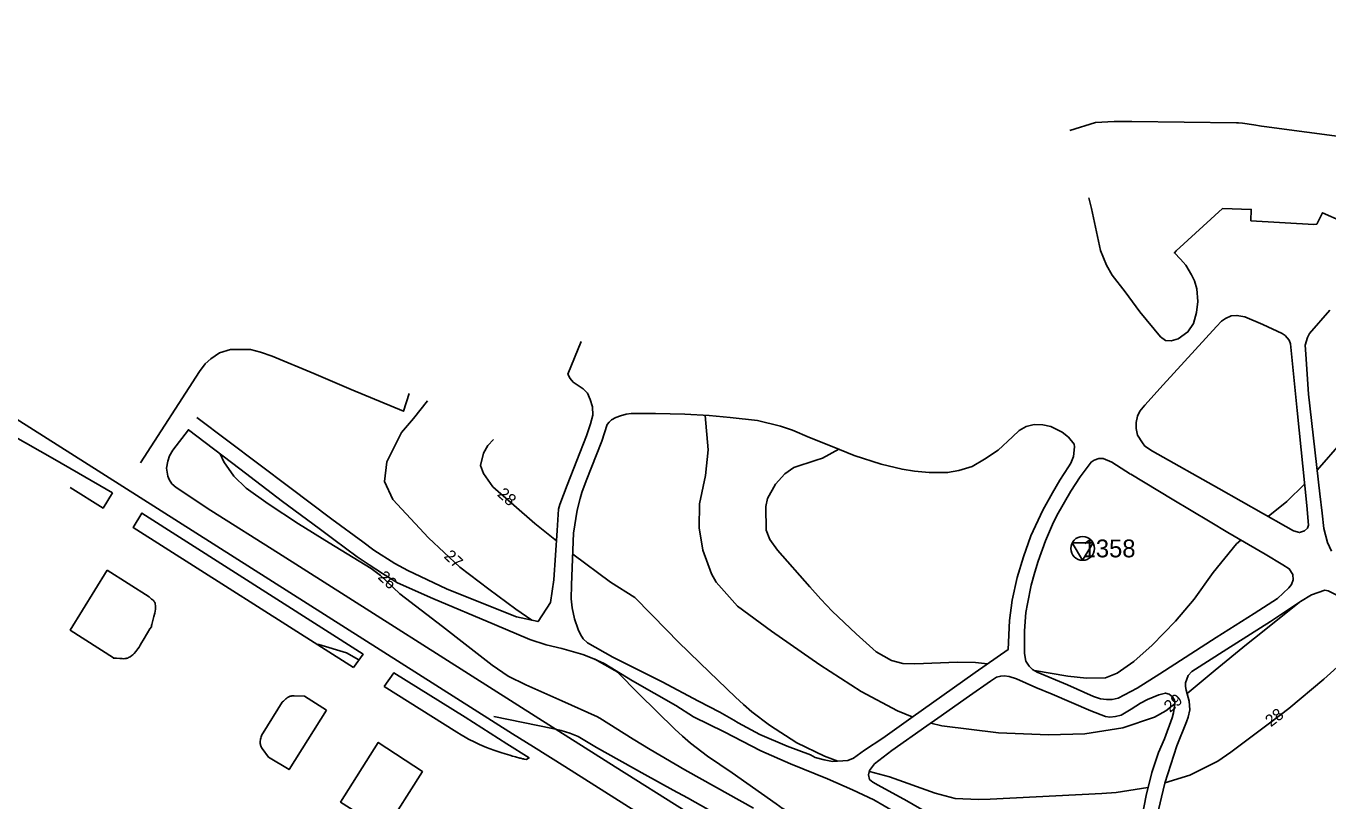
# Model space of a CAD drawing. Extents: x 67169 to 69652, y 20189 to 22818.
# Drawn here: x 69252.8 to 69362.6, y 21251.9 to 21317.2 of the extents above; entities that cross this region are included whole.
import ezdxf

# ---------------------------------------------------------------- set-up
doc = ezdxf.new("R2010")
doc.units = 0
for name, color, linetype in [('HOJDKURVOR_2014', 7, 'Continuous'), ('HOJDKURVOR_2014 5M', 7, 'Continuous'), ('HOJDKURVOR_TEXTER_2014', 7, 'Continuous'), ('MUR_STAKET', 7, 'Continuous'), ('MUR_STAKET_SYMBOL', 7, 'Continuous'), ('STOMPUNKTER', 7, 'Continuous'), ('STOMPUNKTER TEXT', 7, 'Continuous'), ('VAGAR 121', 7, 'Continuous'), ('VAGAR 123', 7, 'Continuous')]:
    doc.layers.add(name, color=color, linetype=linetype)

msp = doc.modelspace()

# ---------------------------------------------------------------- linework, layer by layer
at = {"layer": 'HOJDKURVOR_2014'}
for points in [[(69295.5, 21267.14), (69294.15, 21268.08), (69291.86, 21269.76), (69289.42, 21271.6), (69286.77, 21274.09), (69283.78, 21277.32), (69283.07, 21278.83), (69283.28, 21280.48), (69284.51, 21282.97), (69285.52, 21284.14), (69286.69, 21285.64)], [(69327.58, 21258.98), (69326.35, 21259.5), (69323.27, 21261.14), (69319.78, 21263.37), (69315.7, 21266.21), (69312.83, 21268.33), (69311.04, 21270.35), (69310.64, 21271.04), (69309.93, 21273.04), (69309.6, 21274.94), (69309.65, 21276.96), (69310.14, 21279.35), (69310.36, 21281.49), (69310.12, 21284.41)], [(69297.57, 21273.84), (69295.75, 21275.3), (69292.22, 21278.38), (69291.42, 21279.5), (69291.18, 21280.17), (69291.41, 21281.23), (69291.8, 21281.88), (69292.25, 21282.37)], [(69314.18, 21251.29), (69309.86, 21253.7), (69308.39, 21254.53), (69305.49, 21256.24), (69304.05, 21257.12), (69301.22, 21258.87), (69301.18, 21258.9), (69301.04, 21258.98), (69298.04, 21260.35), (69294.99, 21261.69), (69293.51, 21262.43), (69292.14, 21263.36), (69289.88, 21265.12), (69287.97, 21266.61), (69284.36, 21269.36), (69282.72, 21270.9), (69281.95, 21271.51), (69278.41, 21273.66), (69275.82, 21275.27), (69273.27, 21276.94), (69271.39, 21278.26), (69270.35, 21279.28), (69269.51, 21280.49), (69269.22, 21281.16)], [(69321.31, 21255.26), (69320.19, 21255.68), (69317.84, 21256.8), (69315.55, 21258.29), (69314.06, 21259.41), (69313.36, 21260.02), (69312.67, 21260.65), (69309.69, 21263.52), (69307.82, 21265.34), (69306.9, 21266.26), (69304.17, 21269.05), (69302.14, 21270.34), (69298.96, 21272.72), (69298.95, 21272.73)], [(69360.24, 21268.66), (69357.12, 21266.17), (69355.78, 21265.09), (69353.12, 21262.92), (69350.76, 21260.95)], [(69367.18, 21266.97), (69366.94, 21266.61), (69366.26, 21265.82), (69366.01, 21265.58), (69363.7, 21263.44), (69362.28, 21262.16), (69359.34, 21259.7), (69357.82, 21258.53), (69354.45, 21256), (69353.34, 21255.26), (69350.98, 21254.07), (69348.89, 21253.43)], [(69335.63, 21244.51), (69333.62, 21244.76), (69330.22, 21245.44), (69325.91, 21246.41), (69323.33, 21247.47), (69321.93, 21248.26), (69321.65, 21248.41), (69316.55, 21251.33), (69316.42, 21251.42), (69316.1, 21251.65), (69312.4, 21254.27), (69310.31, 21255.68), (69308.89, 21256.76), (69308.21, 21257.35), (69307.56, 21257.95), (69304.51, 21260.93), (69302.71, 21262.76), (69302.54, 21262.88), (69302.5, 21262.91), (69300.81, 21263.85)], [(69349.73, 21260.09), (69349.51, 21259.91), (69348.97, 21259.49), (69348, 21258.96), (69345.33, 21258.05), (69342.13, 21257.55), (69339.07, 21257.46), (69334.86, 21257.64), (69330.09, 21258.24), (69329.16, 21258.47)], [(69347.46, 21253.02), (69344.77, 21252.62), (69343.57, 21252.54), (69334.14, 21252.06), (69333.16, 21252.03), (69331.2, 21252.1), (69329.52, 21252.55), (69325.65, 21253.92), (69323.97, 21254.39)]]:
    msp.add_lwpolyline(points, dxfattribs=at)
at = {"layer": 'HOJDKURVOR_2014 5M'}
for points in [[(69340.88, 21308.42), (69343.05, 21309.11), (69344.61, 21309.18), (69346.11, 21309.19), (69354.92, 21309.07), (69355.09, 21309.07), (69355.44, 21309.04), (69356.39, 21308.9), (69357.04, 21308.8), (69357.26, 21308.77), (69364.45, 21307.81)], [(69365.96, 21284.63), (69361.73, 21279.78)], [(69333.92, 21263.45), (69332.92, 21263.56), (69331.39, 21263.59), (69327.79, 21263.46), (69326.8, 21263.5), (69325.84, 21263.75), (69324.54, 21264.47), (69322.84, 21265.98), (69320.84, 21267.9), (69319.88, 21268.91), (69318.95, 21269.94), (69316.23, 21273.04), (69315.56, 21273.95), (69315.27, 21274.72), (69315.22, 21276.72), (69315.36, 21277.39), (69316.05, 21278.61), (69316.84, 21279.49), (69317.6, 21280.02), (69319.48, 21280.64), (69320, 21280.81), (69321.38, 21281.57)], [(69360.67, 21278.6), (69359.18, 21277.15), (69357.6, 21275.89)], [(69355.28, 21273.89), (69354.94, 21273.58), (69352.97, 21271.17), (69351.36, 21268.91), (69349.77, 21267.07), (69347.82, 21265.03), (69346.28, 21263.66), (69344.87, 21262.66), (69343.88, 21262.29), (69342.29, 21262.25), (69340.7, 21262.43), (69337.88, 21262.9)], [(69280.92, 21263.79), (69279.88, 21264.38), (69277.52, 21265.09), (69277.4, 21265.1)], [(69314.51, 21248.84), (69308.62, 21252.15), (69307.42, 21252.82), (69305.03, 21254.14), (69300.94, 21256.41), (69299.41, 21257.34), (69298.69, 21257.6), (69297.97, 21257.83), (69297.61, 21257.92), (69297.24, 21258.01), (69292.28, 21259.01)]]:
    msp.add_lwpolyline(points, dxfattribs=at)
at = {"layer": 'MUR_STAKET'}
for points in [[(69265.23, 21281.47), (69264.94, 21281.01), (69264.79, 21280.54), (69264.69, 21279.95), (69264.81, 21279.28), (69264.9, 21279.01), (69265.14, 21278.64), (69265.49, 21278.32), (69268.43, 21276.4), (69274.14, 21272.78), (69296.1, 21258.84)], [(69296.1, 21258.84), (69302.52, 21254.78), (69308.5, 21251), (69318.67, 21244.59), (69325.22, 21240.45), (69336.99, 21232.99), (69342.36, 21229.57), (69352.6, 21223.18), (69355.62, 21221.19), (69360.68, 21217.97), (69370.52, 21211.77), (69376.01, 21208.27), (69380.2, 21208.31), (69385.38, 21216.32)]]:
    msp.add_lwpolyline(points, dxfattribs=at)
at = {"layer": 'MUR_STAKET_SYMBOL'}
for p, q in [((69265.23, 21281.47), (69265.23, 21281.47)), ((69264.76, 21280.34), (69264.76, 21280.34)), ((69264.87, 21279.1), (69264.87, 21279.1)), ((69266.52, 21277.65), (69266.52, 21277.65)), ((69268.12, 21276.6), (69268.12, 21276.6)), ((69269.79, 21275.54), (69269.79, 21275.54)), ((69271.49, 21274.46), (69271.49, 21274.46)), ((69273.21, 21273.37), (69273.21, 21273.37)), ((69274.94, 21272.27), (69274.94, 21272.27)), ((69276.54, 21271.26), (69276.54, 21271.26)), ((69278.27, 21270.15), (69278.27, 21270.15)), ((69280.04, 21269.03), (69280.04, 21269.03)), ((69281.67, 21267.99), (69281.67, 21267.99)), ((69283.39, 21266.91), (69283.39, 21266.91)), ((69285.04, 21265.86), (69285.04, 21265.86)), ((69286.7, 21264.8), (69286.7, 21264.8)), ((69288.4, 21263.73), (69288.4, 21263.73)), ((69290.04, 21262.68), (69290.04, 21262.68)), ((69291.76, 21261.59), (69291.76, 21261.59)), ((69293.47, 21260.51), (69293.47, 21260.51)), ((69295.2, 21259.41), (69295.2, 21259.41)), ((69296.67, 21258.48), (69296.67, 21258.48)), ((69298.43, 21257.37), (69298.43, 21257.37)), ((69300.11, 21256.3), (69300.11, 21256.3)), ((69301.73, 21255.28), (69301.73, 21255.28)), ((69303.47, 21254.18), (69303.47, 21254.18)), ((69305.24, 21253.06), (69305.24, 21253.06)), ((69306.84, 21252.05), (69306.84, 21252.05))]:
    msp.add_line(p, q, dxfattribs=at)
at = {"layer": 'STOMPUNKTER'}
msp.add_lwpolyline([(69341.95, 21272.19), (69342.83, 21273.67), (69341.07, 21273.67)], close=True, dxfattribs=at)
msp.add_circle((69341.95, 21273.19), 1, dxfattribs=at)
at = {"layer": 'VAGAR 121'}
for p, q in [((69259.67, 21271.37), (69263.21, 21269.11)), ((69295.33, 21265.52), (69292.34, 21266.77)), ((69276.31, 21260.73), (69278.19, 21259.54))]:
    msp.add_line(p, q, dxfattribs=at)
for points in [[(69313.16, 21245.38), (69298.29, 21254.81), (69295.63, 21256.45), (69293.87, 21257.57), (69257.76, 21280.45), (69248.82, 21286.11), (69242.96, 21289.82), (69226.82, 21300.08), (69172.15, 21334.79)], [(69260.14, 21277.87), (69257.27, 21279.55), (69255.07, 21280.81), (69251.75, 21282.67), (69250.1, 21283.62), (69248.47, 21284.6), (69242.96, 21287.97), (69225.94, 21298.72), (69174.97, 21331.15), (69174.49, 21331.47), (69174.14, 21331.71), (69173.88, 21331.9), (69173.49, 21332.19), (69173.11, 21332.49), (69173.1, 21332.5)], [(69262.5, 21280.41), (69267.46, 21288.11), (69267.95, 21288.75), (69268.41, 21289.19), (69269.16, 21289.67), (69270.09, 21289.96), (69271.15, 21289.96), (69271.76, 21289.96), (69272.61, 21289.75), (69273.61, 21289.4), (69277.12, 21287.95), (69280.26, 21286.6), (69284.66, 21284.75), (69285.16, 21286.24)], [(69292.34, 21266.77), (69287.14, 21268.97), (69284.18, 21270.29), (69282.9, 21271.08), (69281.77, 21271.8), (69280.77, 21272.49), (69278.8, 21273.93), (69277.57, 21274.87), (69274.47, 21277.15), (69270.88, 21279.9), (69266.53, 21283.2), (69265.23, 21281.47)], [(69256.55, 21278.33), (69259.33, 21276.59), (69260.14, 21277.87)], [(69280.46, 21263.15), (69281.26, 21264.27), (69262.61, 21276.17), (69261.87, 21274.96), (69280.46, 21263.15)], [(69259.67, 21271.37), (69256.57, 21266.3), (69260.21, 21263.97)], [(69263.21, 21269.11), (69263.24, 21269.08), (69263.31, 21269.02), (69263.43, 21268.92), (69263.48, 21268.88), (69263.52, 21268.85), (69263.55, 21268.82), (69263.58, 21268.79), (69263.62, 21268.75), (69263.65, 21268.71), (69263.67, 21268.68), (69263.69, 21268.66), (69263.7, 21268.63), (69263.72, 21268.59), (69263.74, 21268.48), (69263.76, 21268.38), (69263.77, 21268.27), (69263.76, 21268.17), (69263.76, 21268.08), (69263.73, 21267.89), (69263.7, 21267.73), (69263.62, 21267.44), (69263.5, 21267), (69263.45, 21266.78), (69263.42, 21266.68), (69263.41, 21266.57)], [(69263.41, 21266.57), (69263.29, 21266.41), (69263.08, 21266.07), (69262.72, 21265.46), (69262.59, 21265.23), (69262.47, 21265.03), (69262.37, 21264.87), (69262.27, 21264.73), (69262.1, 21264.5), (69261.96, 21264.34), (69261.85, 21264.23), (69261.76, 21264.16), (69261.62, 21264.06), (69261.48, 21263.98), (69261.41, 21263.95), (69261.35, 21263.93), (69261.29, 21263.91), (69261.22, 21263.9), (69261.16, 21263.9), (69261.05, 21263.89), (69260.94, 21263.9), (69260.76, 21263.91), (69260.47, 21263.94), (69260.33, 21263.95), (69260.27, 21263.95), (69260.2, 21263.95)], [(69295.02, 21255.39), (69295.26, 21255.53), (69293.4, 21256.72), (69289.87, 21258.96), (69283.85, 21262.7), (69283.05, 21261.54)], [(69283.05, 21261.54), (69289.17, 21257.69), (69289.54, 21257.46), (69289.87, 21257.27), (69290.16, 21257.11), (69290.68, 21256.85), (69291.08, 21256.67), (69291.68, 21256.41), (69292.29, 21256.18), (69292.63, 21256.06), (69292.88, 21255.98), (69293.26, 21255.86), (69293.64, 21255.75), (69293.88, 21255.67), (69294, 21255.64), (69294.12, 21255.61), (69294.48, 21255.52), (69294.57, 21255.5), (69294.72, 21255.46), (69294.79, 21255.44), (69294.86, 21255.42), (69295.02, 21255.39)], [(69273.29, 21255.59), (69272.74, 21256.33), (69272.69, 21256.4), (69272.66, 21256.47), (69272.63, 21256.54), (69272.61, 21256.6), (69272.6, 21256.67), (69272.59, 21256.73), (69272.59, 21256.79), (69272.59, 21256.84), (69272.59, 21256.95), (69272.61, 21257.04), (69272.62, 21257.12), (69272.64, 21257.19), (69272.67, 21257.31), (69272.71, 21257.4), (69272.73, 21257.46), (69272.78, 21257.56), (69272.83, 21257.64), (69274.44, 21260.23)], [(69274.44, 21260.23), (69274.48, 21260.26), (69274.55, 21260.32), (69274.67, 21260.43), (69274.76, 21260.51), (69274.83, 21260.57), (69274.88, 21260.61), (69274.92, 21260.64), (69274.96, 21260.66), (69275, 21260.68), (69275.05, 21260.7), (69275.12, 21260.72), (69275.19, 21260.74), (69275.26, 21260.75), (69275.32, 21260.76), (69275.44, 21260.77), (69276.31, 21260.73)], [(69278.19, 21259.54), (69275.02, 21254.54), (69273.29, 21255.59)], [(69283.11, 21249.37), (69286.27, 21254.38), (69282.55, 21256.84), (69279.37, 21251.81), (69283.15, 21249.4)]]:
    msp.add_lwpolyline(points, dxfattribs=at)
at = {"layer": 'VAGAR 123'}
for points in [[(69363.83, 21300.75), (69362.18, 21301.5), (69361.7, 21300.53), (69361.45, 21300.5), (69356.15, 21300.82), (69356.17, 21301.77), (69353.75, 21301.86), (69349.83, 21298.27), (69349.69, 21298.11), (69350.21, 21297.59), (69350.65, 21297.08), (69351.14, 21296.27), (69351.39, 21295.76), (69351.59, 21295.08), (69351.67, 21294), (69351.56, 21293.08), (69351.29, 21292.15), (69350.83, 21291.44), (69350.01, 21290.87), (69349.41, 21290.68), (69348.94, 21290.73), (69348.53, 21291.03), (69346.78, 21293.14), (69345.55, 21294.82), (69344.43, 21296.23), (69343.97, 21297.06), (69343.47, 21298.31), (69343.03, 21300.29), (69342.69, 21301.84), (69342.48, 21302.74)], [(69362.94, 21272.96), (69362.6, 21273.68), (69362.3, 21274.86), (69362.14, 21276.17), (69361.96, 21277.78), (69361.01, 21286.2), (69360.78, 21289.58), (69360.71, 21290.33), (69360.92, 21290.98), (69361.08, 21291.32), (69362.8, 21293.27)], [(69347.84, 21281.4), (69353.44, 21278.23), (69359.09, 21275.05), (69359.74, 21274.66), (69360.25, 21274.53), (69360.65, 21274.67), (69360.93, 21274.89), (69361, 21275.14), (69360.85, 21276.8), (69360.05, 21284.83), (69359.47, 21290.43), (69359.37, 21290.76), (69359.04, 21291.13), (69358.78, 21291.31), (69357.15, 21292.07), (69355.63, 21292.71), (69354.97, 21292.83), (69354.48, 21292.81), (69354, 21292.59), (69353.66, 21292.35), (69353.23, 21291.9), (69348.74, 21286.98), (69347.19, 21285.28), (69346.78, 21284.75), (69346.57, 21284.33), (69346.47, 21283.82), (69346.47, 21283.31), (69346.57, 21282.75), (69347, 21282.09), (69347.21, 21281.82), (69347.84, 21281.4)], [(69299.67, 21290.65), (69298.52, 21287.87), (69298.73, 21287.51), (69298.97, 21287.22), (69299.82, 21286.64), (69300.18, 21286.27), (69300.42, 21285.76), (69300.62, 21285.12), (69300.65, 21284.42), (69300.45, 21283.69), (69300.11, 21282.67), (69298.48, 21278.53), (69297.85, 21276.9), (69297.75, 21276.51), (69297.63, 21274.71), (69297.34, 21270.53), (69297.08, 21268.64), (69296.02, 21267.02), (69294.19, 21267.43), (69293.29, 21267.78), (69288.31, 21269.79), (69285.05, 21271.32), (69283.93, 21271.91), (69282.17, 21273.03), (69281.25, 21273.76), (69278.64, 21275.66), (69275.09, 21278.33), (69267.23, 21284.22)], [(69327.45, 21258.89), (69332.89, 21262.73), (69335.67, 21264.66), (69335.79, 21267.12), (69336.02, 21268.84), (69336.43, 21270.75), (69336.95, 21272.49), (69337.59, 21274.26), (69338.59, 21276.41), (69339.4, 21277.89), (69340.04, 21278.95), (69340.76, 21280.06), (69340.96, 21280.37), (69341.19, 21280.95), (69341.26, 21281.76), (69341.24, 21281.97), (69340.75, 21282.57), (69340.23, 21283), (69339.28, 21283.46), (69338.59, 21283.61), (69337.87, 21283.64), (69337.18, 21283.47), (69336.59, 21283.12), (69336.03, 21282.61), (69334.84, 21281.48), (69333.68, 21280.73), (69332.64, 21280.11), (69331.52, 21279.76), (69330.56, 21279.59), (69329.02, 21279.58), (69327.77, 21279.7), (69326.72, 21279.87), (69324.97, 21280.3), (69322.69, 21281.03), (69320.84, 21281.78), (69318.91, 21282.55), (69317.47, 21283.16), (69316.48, 21283.5), (69314.52, 21283.97), (69312.23, 21284.22), (69310.44, 21284.39), (69308.4, 21284.52), (69305.92, 21284.57), (69304.24, 21284.58), (69303.88, 21284.58), (69303.46, 21284.5), (69302.98, 21284.37), (69302.58, 21284.23), (69302.22, 21284.03), (69302.02, 21283.84), (69301.86, 21283.63), (69301.39, 21282.24), (69300.09, 21278.9), (69299.72, 21277.9), (69299.56, 21277.39), (69299.32, 21276.43), (69299.01, 21274.49), (69298.85, 21270.11), (69298.81, 21268.94), (69298.9, 21268.17), (69299.1, 21267.25), (69299.41, 21266.36), (69299.61, 21265.93), (69299.84, 21265.56), (69300.2, 21265.23), (69302.32, 21264.01), (69306.49, 21261.94), (69309.54, 21260.31), (69311.34, 21259.39), (69312.54, 21258.7)], [(69346.03, 21279.44), (69349.5, 21277.33), (69352.71, 21275.43), (69354.2, 21274.52), (69357.34, 21272.7), (69358.84, 21271.81), (69359.37, 21271.48), (69359.68, 21270.99), (69359.7, 21270.54), (69359.57, 21270.16), (69359.35, 21269.87), (69358.38, 21268.98), (69356.43, 21267.71), (69353.2, 21265.67), (69348.46, 21262.63), (69346.55, 21261.4), (69344.94, 21260.56), (69344.45, 21260.46), (69343.97, 21260.44), (69343.46, 21260.52), (69342.88, 21260.7), (69340.68, 21261.69), (69338.11, 21262.77), (69337.73, 21262.99), (69337.45, 21263.25), (69337.17, 21263.69), (69337.04, 21264.34), (69337.04, 21266.23), (69337.17, 21267.79), (69337.3, 21268.53), (69337.61, 21270.08), (69337.92, 21271.2), (69338.2, 21272.12), (69338.82, 21273.83), (69339.4, 21275.2), (69339.78, 21275.96), (69340.96, 21278.03), (69341.75, 21279.22), (69342.67, 21280.47), (69342.92, 21280.64), (69343.31, 21280.77), (69343.67, 21280.78), (69344.4, 21280.46), (69345.98, 21279.45)], [(69350.86, 21258.95), (69350.98, 21259.58), (69350.93, 21260.31), (69350.68, 21261.23), (69350.64, 21261.55), (69350.64, 21261.87), (69350.86, 21262.48), (69351.16, 21262.8), (69354.12, 21264.7), (69357.79, 21267.04), (69360.33, 21268.72), (69361.26, 21269.27), (69362.39, 21269.67), (69362.65, 21269.62), (69363.33, 21269.28), (69364.4, 21268.59), (69366.48, 21267.4), (69368.81, 21265.96), (69369.27, 21265.58), (69369.69, 21265.05), (69369.95, 21264.44)], [(69309.14, 21259), (69307.65, 21259.94), (69304, 21262.04), (69301.59, 21263.48), (69300.73, 21263.89), (69299.8, 21264.26), (69298.04, 21264.76), (69296.7, 21265.07), (69295.33, 21265.52)], [(69329.75, 21258.89), (69332.4, 21260.76), (69334.17, 21262.01), (69334.68, 21262.33), (69335.04, 21262.42), (69335.33, 21262.46), (69335.76, 21262.4), (69336.36, 21262.19), (69338, 21261.47), (69339.37, 21260.9), (69342.64, 21259.49), (69343.87, 21259.02), (69344.25, 21258.97), (69344.72, 21259.01), (69345.2, 21259.14), (69346.04, 21259.65), (69346.84, 21260.13), (69347.42, 21260.44), (69348.39, 21260.86), (69348.94, 21260.99), (69349.24, 21260.9), (69349.54, 21260.69), (69349.69, 21260.39), (69349.73, 21260.05), (69349.62, 21259.34), (69349.51, 21258.92)], [(69309.14, 21259), (69311.72, 21257.72), (69314.8, 21256.12), (69317.32, 21255.04), (69320.43, 21253.76), (69322.55, 21252.83), (69324.35, 21251.98), (69326.09, 21250.99), (69329.8, 21248.71), (69332.28, 21247.08), (69335.47, 21244.63), (69336.86, 21243.53), (69338.45, 21242.23), (69339.88, 21240.95), (69342.25, 21238.63), (69344.9, 21236.16), (69346.01, 21235.16), (69348.26, 21233.66), (69352.35, 21230.87), (69355.88, 21228.4), (69357.36, 21227.36), (69361.05, 21224.73), (69372.49, 21224.87)], [(69327.45, 21258.89), (69325.11, 21257.19), (69323.55, 21256.17), (69322.62, 21255.52), (69322.16, 21255.32), (69320.86, 21255.23), (69320.14, 21255.36), (69319.4, 21255.56), (69319.01, 21255.8), (69317.02, 21256.51), (69314.72, 21257.49), (69312.89, 21258.48), (69312.54, 21258.7)], [(69330.72, 21249.84), (69327.13, 21251.92), (69324.72, 21253.24), (69324.25, 21253.48), (69323.98, 21253.7), (69323.9, 21254.11), (69323.98, 21254.46), (69324.4, 21255.04), (69325.87, 21256.15), (69328.82, 21258.24), (69329.75, 21258.89)], [(69349.51, 21258.92), (69348.86, 21257.14), (69348.36, 21255.99), (69347.78, 21254.3), (69347.3, 21252.37), (69346.74, 21249.46)], [(69384.4, 21219.66), (69382.25, 21221.02), (69376.69, 21224.25), (69372.59, 21226.59), (69361.43, 21226.43), (69348.75, 21235.31), (69348.53, 21235.7), (69348.01, 21239.37), (69347.68, 21242.91), (69347.61, 21244.38), (69347.72, 21247.07), (69348.2, 21250.55), (69348.89, 21253.41), (69349.9, 21256.54), (69350.71, 21258.58), (69350.86, 21258.95)]]:
    msp.add_lwpolyline(points, dxfattribs=at)

# ---------------------------------------------------------------- texts
at = {"layer": 'HOJDKURVOR_TEXTER_2014'}
for s, rotation, p in [('28', 318.8779, (69292.52, 21277.67)), ('27', 317.1293, (69288.02, 21272.45)), ('26', 316.9203, (69282.45, 21270.69)), ('29', 39.7356, (69349.32, 21259.31)), ('28', 37.7938, (69357.83, 21258.1))]:
    msp.add_text(s, height=1, rotation=rotation, dxfattribs=at).set_placement(p)
at = {"layer": 'STOMPUNKTER TEXT'}
msp.add_text('1358', height=1.5, dxfattribs=at).set_placement((69341.95, 21272.44))

doc.saveas('drawing.dxf')
